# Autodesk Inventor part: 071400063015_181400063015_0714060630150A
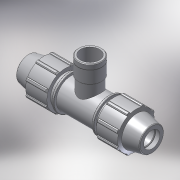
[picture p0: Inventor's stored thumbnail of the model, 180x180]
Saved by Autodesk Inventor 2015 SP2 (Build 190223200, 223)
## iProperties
Created: 2017-02
Part Number: 071400063015_181400063015_0714060630150A
Material: PVC-Piping
Description: PLASSON TEE WITH THREADED FEMALE OFFTAKE 63-1.1/2"-63
Document SubType Name: Modeling
Designer: KIM
Mass: 92.6774 g
Surface Area: 199.44 cm^2
Volume: 66.1981 cm^3
Density: 1.4 g/cm^3
Appearance: Smooth - White
Author: KIM
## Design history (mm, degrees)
derived "07140.ipt"
feature "Solid1::07140.ipt"
feature "Solid2::07140.ipt"
tag "TaggingFeature1"
body "Solid1"
other parameters: "d2" = 63, "d4" = 11.16667, "d5" = 32.16, "d7" = 113, "d11" = 4.46667, "d13" = 120 deg, "d14" = 81.9, "d15" = 12 deg, "d16" = 98.31, "d18" = 3.15, "d19" = 35 deg, "d20" = 17.5 deg, "d21" = 105.09, "d23" = 0, "d25" = 360 deg, "d27" = 2.26, "d33" = 1.26, "d42" = 48.24, "d43" = 3.39, "d46" = 1.89, "d68" = 8.04, "d72" = 95, "d76" = 44.845, "d80" = 1.34535, "d91" = 84.75, "d93" = 113, "d95" = 56.7, "d112" = 27, "d115" = 56.05625, "d116" = 135 deg, "d117" = 51.57175, "d118" = 268, "d119" = 56.7, "d121" = 0, "d122" = 39.69, "d124" = 0, "d128" = 0, "d129" = 6.3, "d130" = 8.1, "d131" = 0.3, "d132" = 0.3, "d133" = 56.05625, "d_" = 63, "E_" = 113, "A_" = 95, "l_" = 113, "l_2" = 27, "Rp_" = 44.845, "H_" = 268
